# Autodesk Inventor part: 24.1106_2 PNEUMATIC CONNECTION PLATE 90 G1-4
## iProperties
Created: 2007-01
Part Number: 24.1106_2 PNEUMATIC CONNECTION PLATE 90 G1-4
Document SubType Name: Modeling
Designer: Andy Moles
Material: Aluminum-6061
Mass: 306.101 g
Surface Area: 230.604 cm^2
Volume: 112.952 cm^3
Density: 2.71 g/cm^3
Author: Andy Moles
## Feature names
1. Extrusion1
2. Hole1
3. Hole2
4. Fillet1
5. Hole3
6. Hole4
7. Extrusion2
8. Chamfer1
